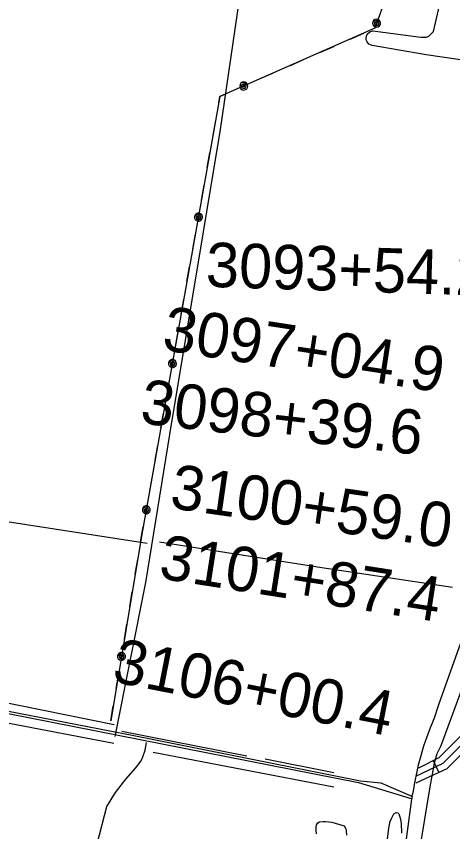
# Model space of a CAD drawing. Extents: x 3279314 to 3317160, y 734079 to 759431.
# Drawn here: x 3292879 to 3293860, y 743558 to 745391 of the extents above; entities that cross this region are included whole.
import ezdxf

# ---------------------------------------------------------------- set-up
doc = ezdxf.new("R2010")
doc.units = 0
for name, color, linetype in [('V-DTCH-CNTR', 7, 'Continuous'), ('V-LEVE-TOET', 7, 'Continuous'), ('V-ROAD-CNTR', 7, 'Continuous'), ('V-SITE-VEGE', 7, 'Continuous'), ('V-SURV-IDEN', 7, 'Continuous'), ('V-TOPO-SHOR', 7, 'Continuous'), ('V-UTIL-LINE', 7, 'Continuous')]:
    doc.layers.add(name, color=color, linetype=linetype)

msp = doc.modelspace()

# ---------------------------------------------------------------- linework, layer by layer
at = {"layer": 'V-DTCH-CNTR'}
for points in [[(3293101.5, 743772.6), (3293170.6, 744118.5), (3293224.8, 744450.9), (3293338.3, 745136), (3293456.5, 745947.2)], [(3292876.7, 742485.5), (3292893.6, 742542.7), (3292904.7, 742589.8), (3292907.6, 742607.2), (3292906.4, 742624.7), (3292906.1, 742639), (3292903.5, 742662.7), (3292903.8, 742682.2), (3292912.8, 742755), (3292933.5, 742844.5), (3292961.7, 742928.2), (3292979.2, 743017.8), (3293001.2, 743186.4), (3293061.4, 743531.4), (3293082.9, 743615.3), (3293102, 743646.2), (3293125.6, 743676.6), (3293147.6, 743701.4), (3293160.3, 743717.6), (3293164, 743726.8), (3293169.4, 743741.6), (3293171.7, 743758.6)]]:
    msp.add_lwpolyline(points, dxfattribs=at)
at = {"layer": 'V-LEVE-TOET'}
msp.add_lwpolyline([(3293931.3, 744015.8), (3293833.3, 743751.4), (3293824.6, 743733.4), (3293818.8, 743712.2), (3293809.1, 743659.5), (3293784.9, 743513.9)], dxfattribs=at)
at = {"layer": 'V-ROAD-CNTR'}
msp.add_line((3293816.1, 743718.3), (3293828.9, 743691.2), dxfattribs=at)
for points in [[(3285804, 745106.6), (3286839.3, 744928.3), (3288316.6, 744671.5), (3289563.3, 744445.8), (3289757.2, 744406.6), (3289783.3, 744405.9), (3289808.6, 744410.8), (3289837, 744409), (3290040.5, 744367.9), (3290276.8, 744314.1), (3290639.1, 744241.5), (3291553.8, 744074.9), (3292369.4, 743920.3), (3293648.3, 743668.9), (3293768.9, 743632.2)], [(3285804, 745106.6), (3286839.3, 744928.3), (3288316.6, 744671.5), (3289563.3, 744445.8), (3289757.2, 744406.6), (3289783.3, 744405.9), (3289808.6, 744410.8), (3289837, 744409), (3290040.5, 744367.9), (3290276.8, 744314.1), (3290639.1, 744241.5), (3291553.8, 744074.9), (3292369.4, 743920.3), (3293648.3, 743668.9), (3293768.9, 743632.2)], [(3286041.8, 745070.6), (3286480.7, 744992.5), (3289793.8, 744424.5), (3293143.2, 743774.6), (3293652.8, 743672.8), (3293698.7, 743668.4), (3293770.2, 743637.2)], [(3293818.3, 743812.2), (3293830.1, 743846.7), (3293919.1, 744096.1)], [(3293777.3, 743683.4), (3293838.7, 743712.5), (3293915, 743788.9), (3293968.7, 743791.1), (3294008.3, 743618.1), (3294172.3, 743587.7), (3294401.5, 743556.5), (3294423.8, 743567.6), (3294446.5, 743580.7), (3294462.7, 743600.1), (3294469.3, 743623.7), (3294536.5, 743889.5), (3294595.6, 744090.2)], [(3293784.2, 743702.2), (3293829.9, 743724.9), (3293908.5, 743803.6), (3293955.3, 743805.6)], [(3293777.9, 743668.1), (3293847.5, 743700), (3293921.5, 743774.1), (3293943, 743775)], [(3293528.9, 741526.8), (3293531.6, 741611), (3293535.4, 741713.4), (3293541.9, 741770.8), (3293546.3, 741831.1), (3293557.9, 741910.4), (3293585.1, 742118.9), (3293606.9, 742315.5), (3293648.2, 742720.4), (3293678.2, 743011.9), (3293732.9, 743368.5), (3293770.3, 743642.6)]]:
    msp.add_lwpolyline(points, dxfattribs=at)
msp.add_arc((3294402.9, 743555.5), 638.6, 156.2893, 172.1554, dxfattribs=at)
at = {"layer": 'V-SITE-VEGE'}
for points in [[(3294120.1, 745257.7), (3293800.4, 745304.3), (3293679.6, 745325.1), (3293672, 745328.3), (3293667.9, 745333.2), (3293665.5, 745337.7), (3293665.6, 745343.6), (3293667.7, 745350.3), (3293673.8, 745355.5), (3293681.1, 745358.4), (3293788.3, 745343.6), (3293801.1, 745344.2), (3293806.6, 745346.3), (3293812, 745351.5), (3293816.9, 745356.9), (3293865.9, 745568)], [(3293708.5, 743499.3), (3293716.9, 743566.6), (3293717.9, 743572.9), (3293719.1, 743579.5), (3293722.4, 743588.2), (3293728, 743598.4), (3293732.9, 743601.6), (3293736.8, 743600.7), (3293739.4, 743598.2), (3293740.9, 743593.6), (3293742.7, 743586.5), (3293744.8, 743577), (3293745.5, 743555.1)], [(3293554.5, 743553.7), (3293553.3, 743561.6), (3293553.7, 743568.6), (3293554.4, 743573.4), (3293556.9, 743578), (3293560.9, 743580.3), (3293568.8, 743581.1), (3293574.1, 743581.2), (3293582.2, 743580.4), (3293588.8, 743579.6), (3293616.3, 743571.4), (3293619.9, 743564.6), (3293620.7, 743560.6), (3293621.8, 743550.3)]]:
    msp.add_lwpolyline(points, dxfattribs=at)
at = {"layer": 'V-TOPO-SHOR'}
for p, q in [((3293116.6, 743784.2), (3293397.6, 743728.7)), ((3293186.9, 743736.7), (3293593, 743659)), ((3293438.4, 743721.8), (3293592.9, 743691.3))]:
    msp.add_line(p, q, dxfattribs=at)
for points in [[(3292323.2, 744339.9), (3292829, 744259.7), (3293173.2, 744207.1)], [(3293201.3, 744210), (3293566.5, 744151.9), (3293860.2, 744107.6)], [(3293099.7, 743798.2), (3292832.8, 743852.4), (3292453.4, 743924.5), (3292355, 743942.6), (3292246.9, 743963.4), (3292257.9, 744044.8), (3292267.6, 744082.8), (3292295.7, 744098.3), (3292356.1, 744087.2), (3292423.5, 744078.9)], [(3292244.1, 743921.2), (3292529.4, 743865.7), (3293098.4, 743757.5)]]:
    msp.add_lwpolyline(points, dxfattribs=at)
at = {"layer": 'V-UTIL-LINE'}
for points in [[(3294823.7, 749101.3), (3294567, 747672.2), (3294455.7, 747427.9), (3294078.1, 746817.4), (3294050.9, 746537.1), (3293880.8, 745906.1), (3293685, 745363.8), (3293337.1, 745210.6), (3293161, 744222.1), (3293091.7, 743807.4)], [(3293689.2, 745375.4), (3293686.4, 745374.7), (3293688.2, 745373.2), (3293690.8, 745373.9), (3293691.5, 745376.8), (3293688.4, 745378.1), (3293684.1, 745376.2), (3293684.4, 745372), (3293688.4, 745369.1), (3293692.6, 745370.9), (3293695, 745374.7), (3293693.4, 745379.2), (3293688.4, 745381.4), (3293680.7, 745378.5), (3293680.2, 745375), (3293681, 745371.6), (3293683.1, 745368.8), (3293686.1, 745366.9), (3293689.6, 745366.4), (3293693, 745367.3), (3293695.8, 745369.4), (3293697.7, 745372.4), (3293698.2, 745375.8), (3293697.3, 745379.2), (3293695.3, 745382.1), (3293692.3, 745383.9), (3293688.8, 745384.4), (3293685.4, 745383.6), (3293682.5, 745381.5), (3293680.7, 745378.5)], [(3293629.5, 745339.3), (3293660.6, 745353)], [(3293561.8, 745309.5), (3293592.9, 745323.2)], [(3293494.1, 745279.7), (3293525.2, 745293.4)], [(3293426.3, 745249.9), (3293457.5, 745263.6)], [(3293390.7, 745234.1), (3293388.2, 745235.6), (3293388.3, 745233.3), (3293390.7, 745231.9), (3293393.2, 745233.4), (3293392, 745236.6), (3293387.7, 745238.4), (3293384.9, 745235.2), (3293385.6, 745230.4), (3293389.8, 745228.5), (3293394.1, 745229.4), (3293396.3, 745233.7), (3293394.4, 745238.9), (3293387, 745242.4), (3293384.1, 745240.4), (3293382.3, 745237.4), (3293381.7, 745233.9), (3293382.4, 745230.5), (3293384.4, 745227.6), (3293387.4, 745225.7), (3293390.9, 745225.1), (3293394.3, 745225.9), (3293397.2, 745227.9), (3293399, 745230.9), (3293399.6, 745234.3), (3293398.9, 745237.8), (3293396.9, 745240.6), (3293393.9, 745242.5), (3293390.5, 745243.1), (3293387, 745242.4)], [(3293334.6, 745196.3), (3293337.1, 745210.6), (3293355, 745218.4)], [(3293321.6, 745123.4), (3293327.6, 745156.9)], [(3293308.6, 745050.6), (3293314.6, 745084)], [(3293295.6, 744977.7), (3293301.6, 745011.2)], [(3293288.8, 744939.3), (3293286.2, 744938.1), (3293288.2, 744936.9), (3293290.7, 744938.1), (3293290.8, 744941.1), (3293287.5, 744941.8), (3293283.6, 744939.2), (3293284.7, 744935.1), (3293289.1, 744933), (3293293, 744935.4), (3293294.7, 744939.6), (3293292.3, 744943.8), (3293287, 744945), (3293279.9, 744940.9), (3293280, 744937.4), (3293281.4, 744934.2), (3293283.9, 744931.7), (3293287.2, 744930.4), (3293290.7, 744930.5), (3293293.9, 744931.9), (3293296.4, 744934.5), (3293297.7, 744937.7), (3293297.6, 744941.2), (3293296.2, 744944.5), (3293293.6, 744946.9), (3293290.4, 744948.2), (3293286.9, 744948.1), (3293283.6, 744946.7), (3293281.2, 744944.2), (3293279.9, 744940.9)], [(3293276, 744867.4), (3293282, 744900.9)], [(3293263, 744794.6), (3293269, 744828.1)], [(3293250, 744721.7), (3293256, 744755.2)], [(3293237, 744648.9), (3293243, 744682.4)], [(3293230.2, 744610.5), (3293227.6, 744609.3), (3293229.6, 744608.1), (3293232.1, 744609.3), (3293232.2, 744612.2), (3293228.9, 744613), (3293225, 744610.4), (3293226.1, 744606.3), (3293230.5, 744604.2), (3293234.4, 744606.6), (3293236.1, 744610.7), (3293233.7, 744614.9), (3293228.4, 744616.2), (3293221.3, 744612.1), (3293221.4, 744608.6), (3293222.8, 744605.3), (3293225.3, 744602.9), (3293228.6, 744601.6), (3293232.1, 744601.7), (3293235.3, 744603.1), (3293237.8, 744605.6), (3293239.1, 744608.9), (3293239, 744612.4), (3293237.6, 744615.6), (3293235, 744618.1), (3293231.8, 744619.4), (3293228.3, 744619.3), (3293225, 744617.9), (3293222.6, 744615.3), (3293221.3, 744612.1)], [(3293217.4, 744538.6), (3293223.4, 744572.1)], [(3293204.4, 744465.8), (3293210.4, 744499.2)], [(3293191.4, 744392.9), (3293197.4, 744426.4)], [(3293178.4, 744320.1), (3293184.4, 744353.5)], [(3293171.6, 744281.7), (3293169, 744280.5), (3293171, 744279.3), (3293173.4, 744280.5), (3293173.6, 744283.4), (3293170.3, 744284.2), (3293166.4, 744281.6), (3293167.5, 744277.5), (3293171.9, 744275.4), (3293175.8, 744277.8), (3293177.5, 744281.9), (3293175.1, 744286.1), (3293169.7, 744287.4), (3293162.7, 744283.3), (3293162.8, 744279.7), (3293164.2, 744276.5), (3293166.7, 744274.1), (3293170, 744272.8), (3293173.5, 744272.9), (3293176.7, 744274.3), (3293179.2, 744276.8), (3293180.4, 744280.1), (3293180.4, 744283.6), (3293179, 744286.8), (3293176.4, 744289.3), (3293173.2, 744290.5), (3293169.7, 744290.5), (3293166.4, 744289.1), (3293164, 744286.5), (3293162.7, 744283.3)], [(3293158.9, 744209.8), (3293161, 744222.1), (3293164.7, 744243.3)], [(3293146.7, 744136.8), (3293152.3, 744170.3)], [(3293134.5, 744063.8), (3293140.1, 744097.3)], [(3293122.4, 743990.8), (3293128, 744024.4)], [(3293115.9, 743952.3), (3293113.3, 743951.1), (3293115.3, 743950), (3293117.8, 743951.2), (3293118, 743954.1), (3293114.6, 743954.8), (3293110.8, 743952.2), (3293111.9, 743948.1), (3293116.3, 743946), (3293120.1, 743948.5), (3293121.8, 743952.7), (3293119.4, 743956.8), (3293114, 743958.1), (3293107.1, 743953.8), (3293107.2, 743950.3), (3293108.6, 743947.1), (3293111.2, 743944.7), (3293114.4, 743943.5), (3293118, 743943.6), (3293121.2, 743945), (3293123.6, 743947.6), (3293124.8, 743950.9), (3293124.7, 743954.4), (3293123.3, 743957.6), (3293120.7, 743960), (3293117.4, 743961.2), (3293113.9, 743961.1), (3293110.7, 743959.7), (3293108.3, 743957.1), (3293107.1, 743953.8)], [(3293103.9, 743880.3), (3293109.5, 743913.9)], [(3293091.7, 743807.4), (3293097.3, 743840.9)]]:
    msp.add_lwpolyline(points, dxfattribs=at)

# ---------------------------------------------------------------- texts
at = {"layer": 'V-SURV-IDEN'}
for s, rotation, p in [('3093+54.2', 358.1617, (3293304.4, 744783)), ('3097+04.9', 351.2885, (3293204.6, 744641.5)), ('3098+39.6', 353.5046, (3293155.7, 744476.3)), ('3100+59.0', 351.7805, (3293221.9, 744286.1)), ('3101+87.4', 351.1018, (3293197.2, 744128.1)), ('3106+00.4', 348.8769, (3293091.8, 743895.9))]:
    msp.add_text(s, height=100, rotation=rotation, dxfattribs=at).set_placement(p)

doc.saveas('drawing.dxf')
